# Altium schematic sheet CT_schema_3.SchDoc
size 295 x 165 mm
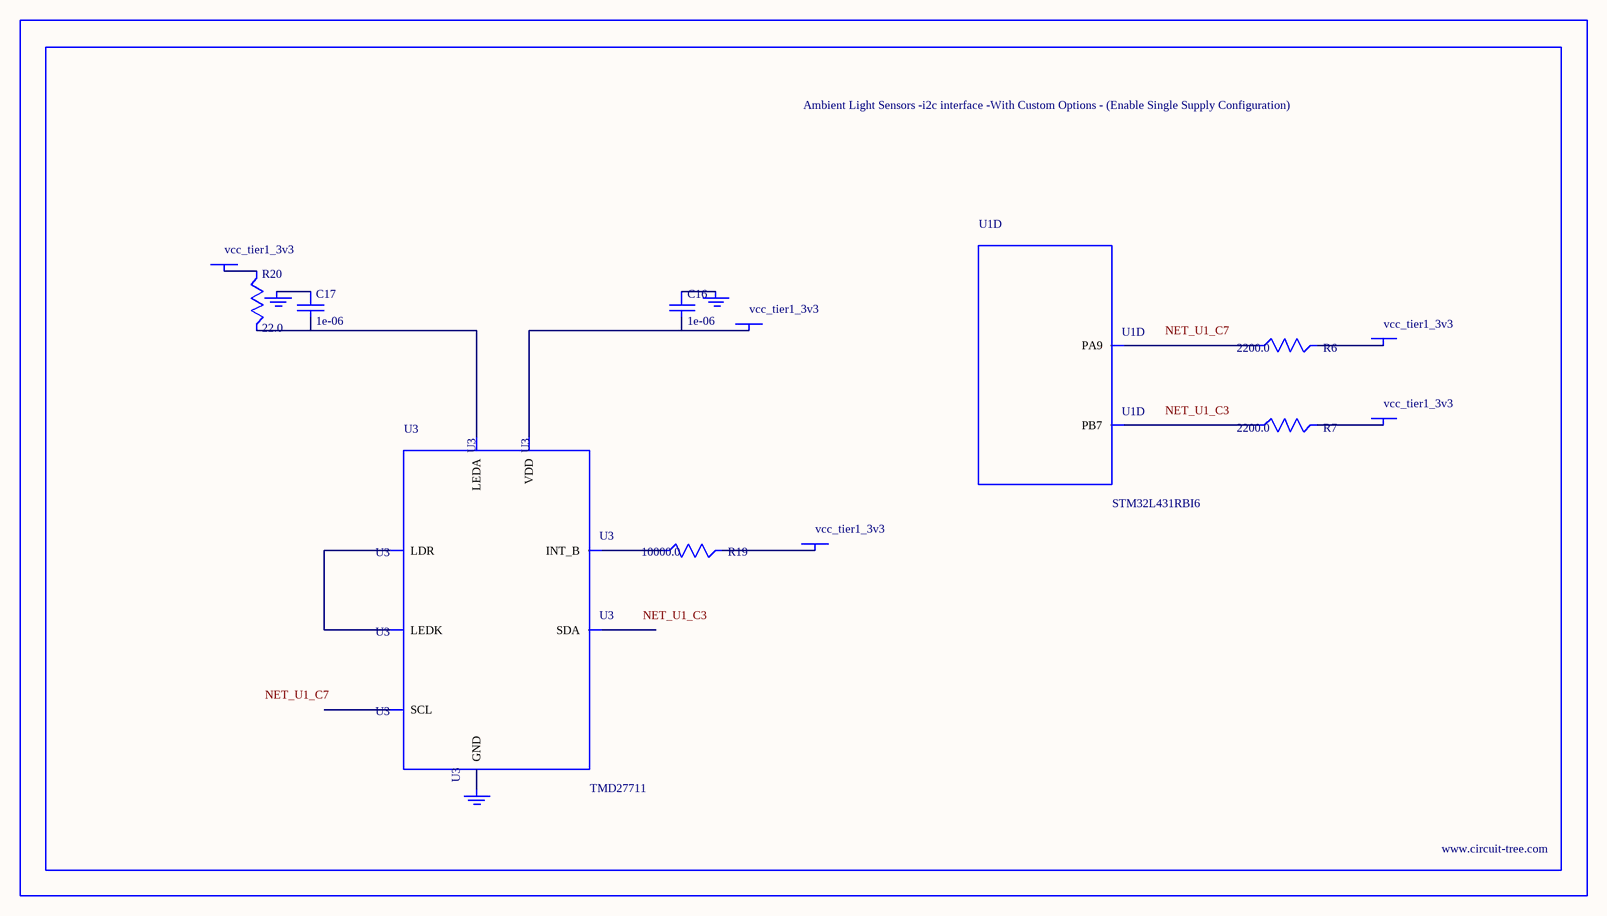
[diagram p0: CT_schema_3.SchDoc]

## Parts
BORDER2  (no value)
C16  1e-06  [C0603]
C17  1e-06  [C0603]
GND_INSTANCE_2_0  (no value)
GND_INSTANCE_2_1  (no value)
GND_INSTANCE_2_2  (no value)
POWER_INSTANCE_2_0  vcc_tier1_3v3
POWER_INSTANCE_2_1  vcc_tier1_3v3
POWER_INSTANCE_2_2  vcc_tier1_3v3
POWER_INSTANCE_2_3  vcc_tier1_3v3
POWER_INSTANCE_2_4  vcc_tier1_3v3
R6  2200.0  [R0603]
R7  2200.0  [R0603]
R19  10000.0  [R0603]
R20  22.0  [R0603]
U1  STM32L431RBI6  [UFBGA64]  (part D of 6)
U3  TMD27711  [SMD-8]

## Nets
NetC16_1: C16.1 GND_INSTANCE_2_0.0(GND)
NetC16_2: C16.2 POWER_INSTANCE_2_0.0(PWR) U3.1(VDD)
NetC17_1: C17.1 GND_INSTANCE_2_1.0(GND)
NetC17_2: C17.2 R20.2 U3.4(LEDA)
NetGND_INSTANCE_2_2_0: GND_INSTANCE_2_2.0(GND) U3.3(GND)
NetPOWER_INSTANCE_2_1_0: POWER_INSTANCE_2_1.0(PWR) R20.1
NetPOWER_INSTANCE_2_2_0: POWER_INSTANCE_2_2.0(PWR) R19.2
NetPOWER_INSTANCE_2_3_0: POWER_INSTANCE_2_3.0(PWR) R6.2
NetPOWER_INSTANCE_2_4_0: POWER_INSTANCE_2_4.0(PWR) R7.2
NetR6_1: R6.1 U1.C7(PA9)
NetR7_1: R7.1 U1.C3(PB7)
NetR19_1: R19.1 U3.7(INT_B)
NetU3_5: U3.5(LEDK) U3.6(LDR)

Not connected (* = marked no-connect by the designer): U3 2(SCL) 8(SDA)

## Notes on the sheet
- Labels drawn without touching a wire or pin: NET_U1_C3, NET_U1_C7

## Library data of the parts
BORDER2 = BORDER_PAGE2
C16 C17 = C0603C105K3RACTU
GND_INSTANCE_2_0-GND_INSTANCE_2_2 = GND
POWER_INSTANCE_2_0-POWER_INSTANCE_2_4 = PWR
R6 R7 = RC0603JR-072K2L
R19 = RC0603JR-0710KL
R20 = RC0603JR-0722RL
